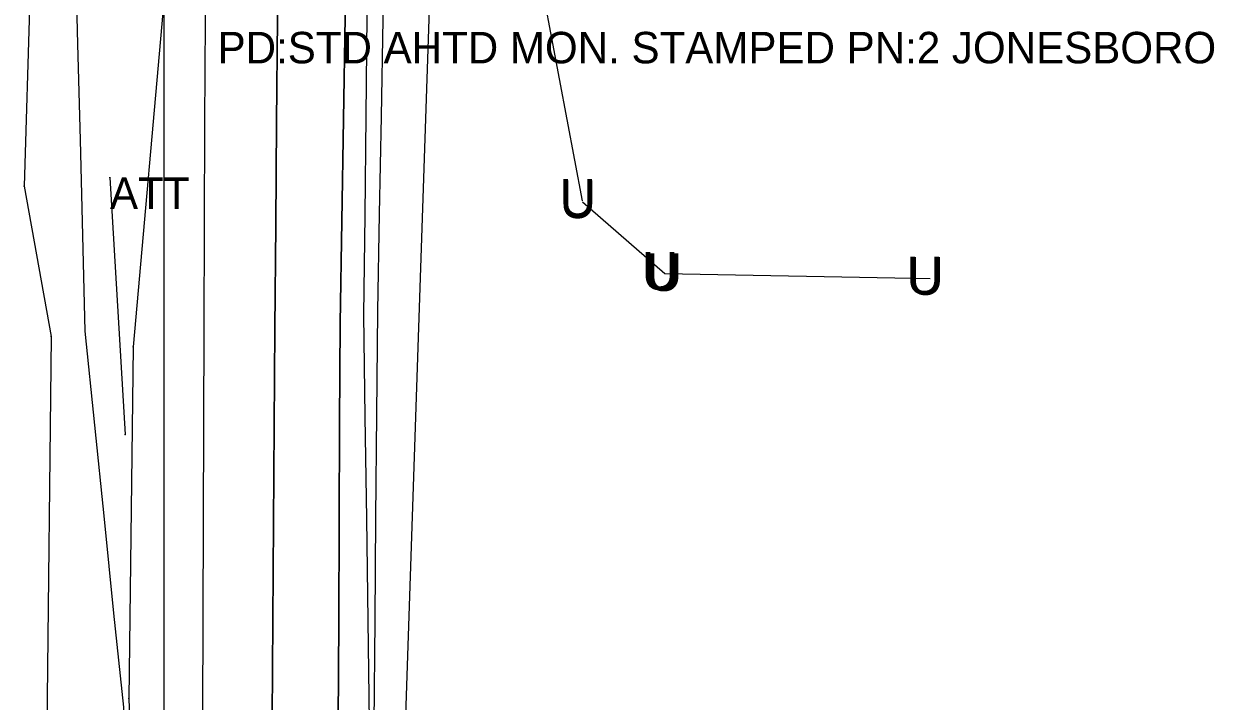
# Model space of a CAD drawing. Extents: x 1707085 to 1720058, y 548761 to 560063.
# Drawn here: x 1712442.1 to 1712631.2, y 550426.5 to 550534.1 of the extents above; entities that cross this region are included whole.
import ezdxf

# ---------------------------------------------------------------- set-up
doc = ezdxf.new("R2010")
doc.units = 0
for name, color, linetype in [('44', 7, 'Continuous'), ('Default', 7, 'Continuous'), ('R_Water Annot', 7, 'Continuous'), ('S_EDGE_PAVEMENT', 7, 'Continuous'), ('S_FIBER_OPTIC_CABLE_ANNOT', 7, 'Continuous'), ('S_GAS_UTILITIES', 7, 'Continuous'), ('S_PAVEMENT_CROWN', 7, 'Continuous'), ('S_PRIMARY_CTL_ANNOT', 7, 'Continuous'), ('S_UNDERGROUND_CABLE', 7, 'Continuous'), ('S_UTILITY_POLE', 7, 'Continuous'), ('S_UTL_PT_SYM', 7, 'Continuous')]:
    doc.layers.add(name, color=color, linetype=linetype)

msp = doc.modelspace()

# ---------------------------------------------------------------- linework, layer by layer
for points in [[(1712497.6, 550680.15), (1712497.36, 550665.48), (1712497.12, 550650.8), (1712496.87, 550636.13), (1712496.63, 550621.46), (1712496.66, 550603.89), (1712496.68, 550586.31), (1712496.71, 550568.74), (1712496.74, 550551.17), (1712496.57, 550535.35), (1712496.4, 550519.52), (1712496.23, 550503.7), (1712496.06, 550487.88), (1712496.27, 550471.69), (1712496.49, 550455.51), (1712496.71, 550439.33), (1712496.93, 550423.15)], [(1712499.77, 550680.44), (1712499.76, 550665.56), (1712499.74, 550650.67), (1712499.72, 550635.78), (1712499.71, 550620.89), (1712499.63, 550603.25), (1712499.55, 550585.61), (1712499.47, 550567.97), (1712499.4, 550550.32), (1712499.11, 550534.87), (1712498.82, 550519.41), (1712498.53, 550503.95), (1712498.24, 550488.49), (1712498.1, 550472.1), (1712497.96, 550455.71), (1712497.82, 550439.31), (1712497.69, 550422.92)], [(1712450.26, 550546.06), (1712450.63, 550530.87), (1712451.01, 550515.67), (1712451.38, 550500.48), (1712451.76, 550485.28), (1712453.29, 550470.36), (1712454.82, 550455.43), (1712456.35, 550440.5), (1712457.89, 550425.57), (1712457.37, 550408.66), (1712456.85, 550391.74), (1712456.33, 550374.83), (1712455.82, 550357.92), (1712457.14, 550352.68), (1712454.4, 550340.57)]]:
    msp.add_lwpolyline(points)
at = {"layer": '44'}
for p, q in [((1712464.32, 550556.31), (1712464.29, 550357.8)), ((1712455.77, 550509.71), (1712458.16, 550468.89))]:
    msp.add_line(p, q, dxfattribs=at)
at = {"layer": 'R_Water Annot'}
for p, q in [((1712443.82, 550562.74), (1712442.13, 550508.33)), ((1712442.13, 550508.33), (1712446.43, 550484.44)), ((1712446.43, 550484.44), (1712445.25, 550380.8))]:
    msp.add_line(p, q, dxfattribs=at)
at = {"layer": 'S_EDGE_PAVEMENT'}
for points in [[(1712495.13, 550823.13), (1712494.92, 550798.66), (1712494.59, 550779.89), (1712494.26, 550761.12), (1712494.05, 550740.6), (1712493.83, 550720.08), (1712493.62, 550699.57), (1712493.41, 550679.05), (1712493.32, 550664.55), (1712493.24, 550650.05), (1712493.16, 550635.55), (1712493.07, 550621.05), (1712493.15, 550603.63), (1712493.23, 550586.21), (1712493.31, 550568.79), (1712493.38, 550551.37), (1712493.12, 550535.16), (1712492.85, 550518.96), (1712492.58, 550502.75), (1712492.31, 550486.54), (1712492.24, 550470.74), (1712492.17, 550454.95), (1712492.11, 550439.15), (1712492.04, 550423.35)], [(1712472.07, 550700.51), (1712471.86, 550680.8), (1712471.78, 550665.91), (1712471.7, 550651.01), (1712471.62, 550636.12), (1712471.54, 550621.23), (1712471.39, 550603.69), (1712471.24, 550586.15), (1712471.09, 550568.61), (1712470.94, 550551.07), (1712470.87, 550534.75), (1712470.79, 550518.44), (1712470.72, 550502.12), (1712470.65, 550485.8), (1712470.61, 550470.5), (1712470.56, 550455.2), (1712470.52, 550439.9), (1712470.48, 550424.59)], [(1712492.04, 550423.35), (1712492.11, 550439.15), (1712492.17, 550454.95), (1712492.24, 550470.74), (1712492.31, 550486.54), (1712492.58, 550502.75), (1712492.85, 550518.96), (1712493.12, 550535.16), (1712493.38, 550551.37), (1712493.31, 550568.79), (1712493.23, 550586.21), (1712493.15, 550603.63), (1712493.07, 550621.05), (1712493.16, 550635.55), (1712493.24, 550650.05), (1712493.32, 550664.55), (1712493.41, 550679.05), (1712493.62, 550699.57)]]:
    msp.add_lwpolyline(points, dxfattribs=at)
at = {"layer": 'S_GAS_UTILITIES'}
for p, q in [((1712464.54, 550540.21), (1712459.44, 550482.79)), ((1712459.44, 550482.79), (1712458.76, 550426.92)), ((1712458.76, 550426.92), (1712459.4, 550410.41))]:
    msp.add_line(p, q, dxfattribs=at)
at = {"layer": 'S_PAVEMENT_CROWN'}
for points in [[(1712481.54, 550423.86), (1712481.65, 550439.32), (1712481.75, 550454.78), (1712481.85, 550470.24), (1712481.96, 550485.7), (1712482.09, 550502.11), (1712482.23, 550518.51), (1712482.37, 550534.91), (1712482.5, 550551.32), (1712482.66, 550568.44), (1712482.82, 550585.57), (1712482.97, 550602.7), (1712483.13, 550619.83), (1712483.2, 550635.1), (1712483.27, 550650.38), (1712483.33, 550665.65), (1712483.4, 550680.93), (1712483.56, 550700.86)], [(1712483.56, 550700.86), (1712483.4, 550680.93), (1712483.33, 550665.65), (1712483.27, 550650.38), (1712483.2, 550635.1), (1712483.13, 550619.83), (1712482.97, 550602.7), (1712482.82, 550585.57), (1712482.66, 550568.44), (1712482.5, 550551.32), (1712482.37, 550534.91), (1712482.23, 550518.51), (1712482.09, 550502.11), (1712481.96, 550485.7), (1712481.85, 550470.24), (1712481.75, 550454.78), (1712481.65, 550439.32), (1712481.54, 550423.86)]]:
    msp.add_lwpolyline(points, dxfattribs=at)
at = {"layer": 'S_UNDERGROUND_CABLE'}
for p, q in [((1712530.81, 550505.98), (1712520.43, 550561.06)), ((1712543.88, 550494.4), (1712530.82, 550505.79)), ((1712586.06, 550493.61), (1712543.88, 550494.4))]:
    msp.add_line(p, q, dxfattribs=at)
at = {"layer": 'S_UTILITY_POLE'}
msp.add_lwpolyline([(1712497.7, 549518.48), (1712500.91, 549949.57), (1712500.58, 550149.34), (1712502.49, 550416.34), (1712509.79, 550634.49), (1712512.76, 550903.53), (1712513.37, 551033.49), (1712513.87, 551133.13), (1712444.45, 551132.54)], dxfattribs=at)
at = {"layer": 'S_UTL_PT_SYM'}
for points in [[(1712455.77, 550509.71), (1712455.77, 550509.76), (1712455.77, 550509.71), (1712455.72, 550509.71), (1712455.77, 550509.71), (1712455.77, 550509.66), (1712455.77, 550509.71), (1712455.82, 550509.71)], [(1712442.13, 550508.33), (1712442.13, 550508.38), (1712442.13, 550508.33), (1712442.08, 550508.33), (1712442.13, 550508.33), (1712442.13, 550508.28), (1712442.13, 550508.33), (1712442.18, 550508.33)], [(1712446.43, 550484.44), (1712446.43, 550484.49), (1712446.43, 550484.44), (1712446.38, 550484.44), (1712446.43, 550484.44), (1712446.43, 550484.39), (1712446.43, 550484.44), (1712446.48, 550484.44)], [(1712459.44, 550482.79), (1712459.44, 550482.84), (1712459.44, 550482.79), (1712459.39, 550482.79), (1712459.44, 550482.79), (1712459.44, 550482.74), (1712459.44, 550482.79), (1712459.49, 550482.79)], [(1712458.16, 550468.89), (1712458.16, 550468.94), (1712458.16, 550468.89), (1712458.11, 550468.89), (1712458.16, 550468.89), (1712458.16, 550468.84), (1712458.16, 550468.89), (1712458.21, 550468.89)], [(1712458.76, 550426.92), (1712458.76, 550426.97), (1712458.76, 550426.92), (1712458.71, 550426.92), (1712458.76, 550426.92), (1712458.76, 550426.87), (1712458.76, 550426.92), (1712458.81, 550426.92)]]:
    msp.add_lwpolyline(points, dxfattribs=at)

# ---------------------------------------------------------------- texts
at = {"layer": 'Default'}
for p in [(1712527.18, 550503.44), (1712527.19, 550503.25), (1712540.25, 550491.85), (1712540.88, 550491.68), (1712582.28, 550491.13), (1712582.43, 550491.06)]:
    msp.add_text('U', height=6, rotation=360, dxfattribs=at).set_placement(p)
at = {"layer": 'S_FIBER_OPTIC_CABLE_ANNOT'}
msp.add_text('ATT', height=5, dxfattribs=at).set_placement((1712455.77, 550504.71))
at = {"layer": 'S_PRIMARY_CTL_ANNOT'}
msp.add_text('PD:STD AHTD MON. STAMPED PN:2 JONESBORO', height=5, dxfattribs=at).set_placement((1712472.86, 550527.84))

doc.saveas('drawing.dxf')
